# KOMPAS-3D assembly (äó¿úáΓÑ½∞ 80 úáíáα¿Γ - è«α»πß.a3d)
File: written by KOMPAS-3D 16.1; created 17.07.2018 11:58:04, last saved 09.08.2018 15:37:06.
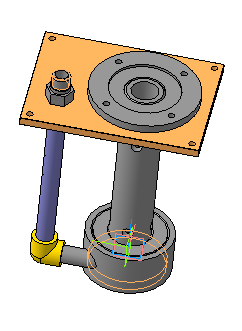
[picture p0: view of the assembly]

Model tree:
1. Булева операция:7
2. Булева операция:8
3. Булева операция:9
4. Булева операция:10
5. Сечение поверхностью:1  (labels: Полипропилен  ГОСТ 26996-86)

Referenced files in Z:\Магна\Магна Ins\Магна ins 10\М10-00.00.000\3Д\: М10-00.30.000 - Обечайка.a3d, М10-00.25.000 - Колонна.a3d, М10-00.20.001 - Плита опорная.m3d, М10-00.20.002 - Фланец.m3d, М10-00.25.000 - Колонна.cdw, М10-00.20.002 - Фланец.cdw
Referenced files in Z:\1 ПКИ 3D\Полипропиленовые фитинги, трубы\: Колено 90гр 32 FV PPR ф. FV PLAST.m3d, Переходник с пластмассовой резьбой наружной 32х1 FV PPR ф.FV Plast.m3d
Referenced files in Z:\1 ПКИ 3D\Полипропиленовые фитинги, трубы\Трубы\: Труба 32 PN10 S=2,9 FV PPR ф. FV PLAST.m3d
Referenced files in \\192.168.87.28\Konstructor_doc\Магна\Магна Ins\Магна ins 10\М10-00.00.000\3Д\: М10-00.30.000 - Обечайка.cdw
Referenced files: graphic.tdp
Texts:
  Body Specification ( left align )
  Body Specificaton ( centered )
  габ. 71, 80
  См. Табл.1
  Колено 90@1~ @2~32 FV PPR ф. "FV PLAST"
  Переходник с пластмассовой резьбой
  наружной 32х1" FV PPR
  ф. "FV PLAST"
  Переходник с пластмассовой резьбой  / наружной 32х1" FV PPR  / ф. "FV PLAST"
  Труба 32 PN10 S=2,9 FV PPR ф. "FV PLAST"
  Ст2сп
